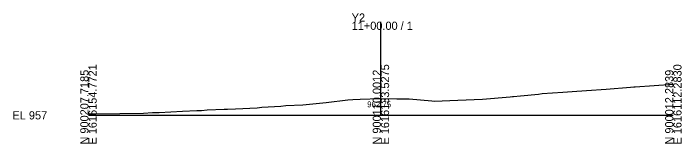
# Model space of a CAD drawing. Extents: x -26 to 1403, y -10 to 2517.
# Drawn here: x -25.7 to 202.8, y 990.3 to 1034.9 of the extents above; entities that cross this region are included whole.
import ezdxf

# ---------------------------------------------------------------- set-up
doc = ezdxf.new("R2010")
doc.units = 0
for name, color, linetype in [('Exist Cross Section Cell', 7, 'Continuous'), ('Exist XS Center Line Elevation Label', 7, 'Continuous'), ('Exist XS Ground Line', 7, 'Continuous')]:
    doc.layers.add(name, color=color, linetype=linetype)

msp = doc.modelspace()

# ---------------------------------------------------------------- linework, layer by layer
at = {"layer": 'Exist Cross Section Cell'}
for p, q in [((100, 1000), (100, 1032.06)), ((0, 1000), (100, 1000)), ((100, 1000), (200, 1000))]:
    msp.add_line(p, q, dxfattribs=at)
at = {"layer": 'Exist XS Ground Line'}
for p, q in [((186.98, 1009.81), (200, 1010.69)), ((155.19, 1007.45), (162.26, 1007.89)), ((162.26, 1007.89), (165.42, 1008.17)), ((165.42, 1008.17), (170.33, 1008.54)), ((170.33, 1008.54), (177, 1008.98)), ((177, 1008.98), (185.38, 1009.69)), ((185.38, 1009.69), (186.52, 1009.78)), ((186.52, 1009.78), (186.98, 1009.81)), ((92.95, 1005.53), (99.67, 1005.75)), ((99.67, 1005.75), (100, 1005.75)), ((100, 1005.75), (105.4, 1005.65)), ((105.4, 1005.65), (109.64, 1005.68)), ((109.64, 1005.68), (117.39, 1004.97)), ((134.72, 1005.49), (144.18, 1006.37)), ((144.18, 1006.37), (144.97, 1006.43)), ((144.97, 1006.43), (145.31, 1006.44)), ((145.31, 1006.44), (147.73, 1006.7)), ((147.73, 1006.7), (153.85, 1007.27)), ((153.85, 1007.27), (155.19, 1007.45)), ((65.78, 1003.17), (67.52, 1003.32)), ((67.52, 1003.32), (73.3, 1003.59)), ((73.3, 1003.59), (81.28, 1004.44)), ((81.28, 1004.44), (88.69, 1005.27)), ((88.69, 1005.27), (90.45, 1005.42)), ((90.45, 1005.42), (92.95, 1005.53)), ((117.39, 1004.97), (118.17, 1004.89)), ((118.17, 1004.89), (126.27, 1005.18)), ((126.27, 1005.18), (134.72, 1005.49)), ((21.92, 1000.93), (24.18, 1000.99)), ((24.18, 1000.99), (32.14, 1001.47)), ((32.14, 1001.47), (37.08, 1001.69)), ((37.08, 1001.69), (38.7, 1001.69)), ((38.7, 1001.69), (40.57, 1001.86)), ((40.57, 1001.86), (46.42, 1002.1)), ((46.42, 1002.1), (46.8, 1002.11)), ((46.8, 1002.11), (47.56, 1002.15)), ((47.56, 1002.15), (50.3, 1002.24)), ((50.3, 1002.24), (57.67, 1002.62)), ((57.67, 1002.62), (59.33, 1002.74)), ((59.33, 1002.74), (65.78, 1003.17)), ((0, 1000.52), (1.1, 1000.54)), ((1.1, 1000.54), (10.69, 1000.6)), ((10.69, 1000.6), (18.79, 1000.75)), ((18.79, 1000.75), (21.92, 1000.93))]:
    msp.add_line(p, q, dxfattribs=at)

# ---------------------------------------------------------------- texts
at = {"layer": 'Exist Cross Section Cell'}
for s, p in [('Y2', (90, 1032.06)), ('11+00.00 / 1', (90, 1029.26)), ('EL 957', (-26, 998.6))]:
    msp.add_text(s, height=2.8, dxfattribs=at).set_placement(p)
for s, p in [('E 1616154.7721', (2.8, 990)), ('E 1616133.5275', (102.8, 990)), ('E 1616112.2830', (202.8, 990)), ('N 900207.7185', (0, 990)), ('N 900110.0012', (100, 990)), ('N 900012.2839', (200, 990))]:
    msp.add_text(s, height=2.8, rotation=90, dxfattribs=at).set_placement(p)
at = {"layer": 'Exist XS Center Line Elevation Label'}
msp.add_text('962.75', height=2, dxfattribs=at).set_placement((95.31, 1002.75))

doc.saveas('drawing.dxf')
